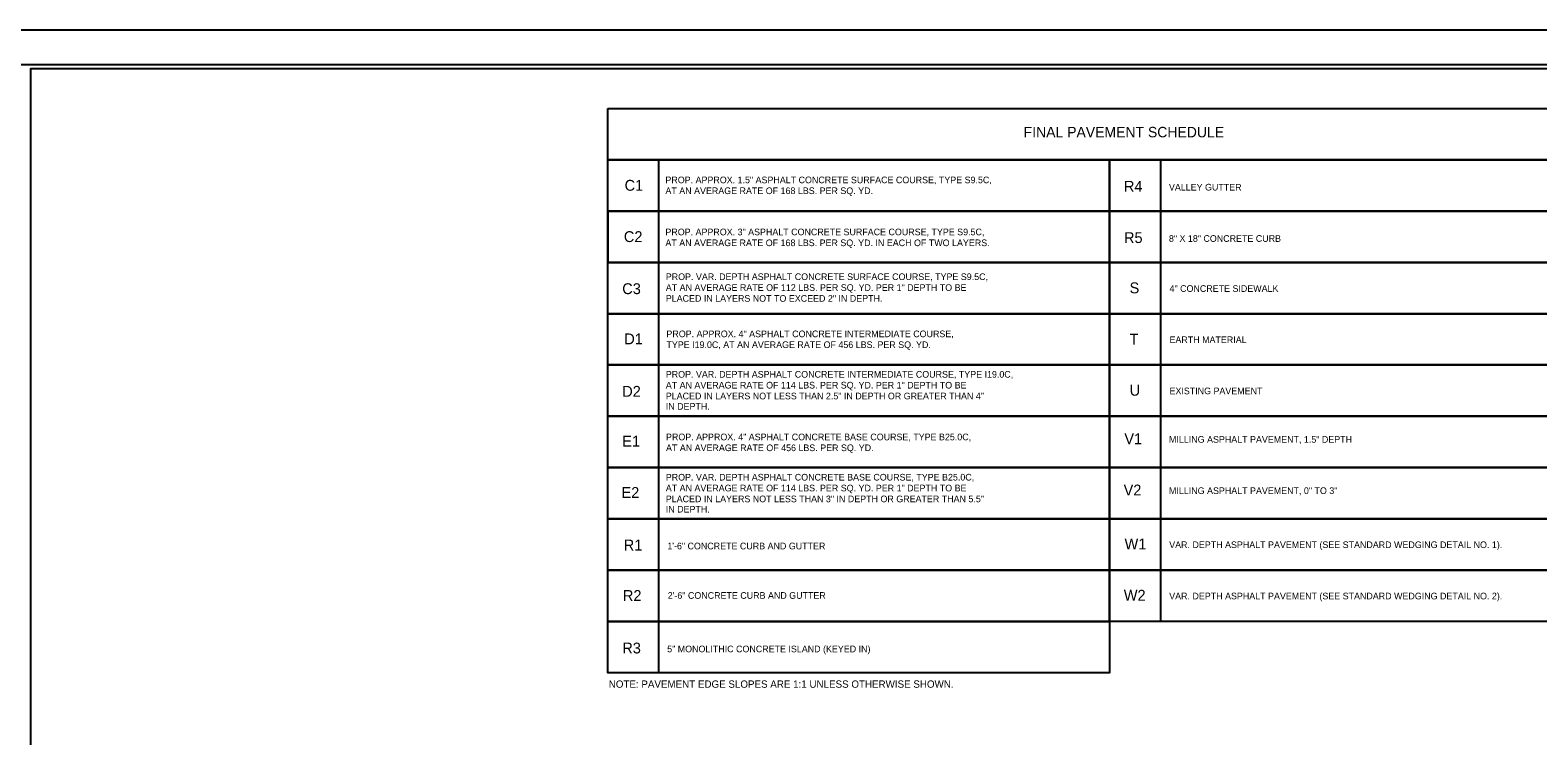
# Model space of a CAD drawing. Extents: x 957297 to 961629, y 830661 to 840840.
# Drawn here: x 958878 to 959856, y 840382 to 840840 of the extents above; entities that cross this region are included whole.
import ezdxf

# ---------------------------------------------------------------- set-up
doc = ezdxf.new("R2010")
doc.units = 0
for name, color, linetype in [('Old_Level_1', 7, 'Continuous'), ('Old_Level_19', 7, 'Continuous'), ('Old_Level_21', 7, 'Continuous'), ('Prop Pavement Schedule Description CELL', 7, 'Continuous'), ('Sheet Plot Border Inside CELL', 7, 'Continuous'), ('Sheet Plot Border Outside CELL', 7, 'Continuous'), ('Sheet Typical CELL', 7, 'Continuous')]:
    doc.layers.add(name, color=color, linetype=linetype)

msp = doc.modelspace()

# ---------------------------------------------------------------- linework, layer by layer
at = {"layer": 'Old_Level_1'}
msp.add_line((959252.25, 840722.31), (959252.25, 840689.02), dxfattribs=at)
at = {"layer": 'Old_Level_19'}
msp.add_lwpolyline([(959252.25, 840788.91), (959903.38, 840788.91), (959903.38, 840755.61), (959252.25, 840755.61)], close=True, dxfattribs=at)
for points in [[(959285.55, 840722.31), (959252.25, 840722.31), (959252.25, 840755.61), (959577.81, 840755.61), (959577.81, 840722.31), (959285.55, 840722.31), (959285.55, 840755.61)], [(959611.11, 840722.32), (959577.81, 840722.32), (959577.81, 840755.61), (959903.38, 840755.61), (959903.38, 840722.32), (959611.11, 840722.32), (959611.11, 840755.61)], [(959285.55, 840689.02), (959252.25, 840689.02), (959252.25, 840722.31), (959577.81, 840722.31), (959577.81, 840689.02), (959285.55, 840689.02), (959285.55, 840722.31)], [(959611.11, 840689.02), (959577.81, 840689.02), (959577.81, 840722.3), (959903.38, 840722.3), (959903.38, 840689.02), (959611.11, 840689.02), (959611.11, 840722.3)], [(959285.55, 840655.72), (959252.25, 840655.72), (959252.25, 840689.02), (959577.81, 840689.02), (959577.81, 840655.72), (959285.55, 840655.72), (959285.55, 840689.02)], [(959611.11, 840655.72), (959577.81, 840655.72), (959577.81, 840689.02), (959903.38, 840689.02), (959903.38, 840655.72), (959611.11, 840655.72), (959611.11, 840689.02)], [(959285.55, 840622.42), (959252.25, 840622.42), (959252.25, 840655.72), (959577.81, 840655.72), (959577.81, 840622.42), (959285.55, 840622.42), (959285.55, 840655.72)], [(959611.11, 840622.42), (959577.81, 840622.42), (959577.81, 840655.72), (959903.38, 840655.72), (959903.38, 840622.42), (959611.11, 840622.42), (959611.11, 840655.72)], [(959285.55, 840589.12), (959252.25, 840589.12), (959252.25, 840622.42), (959577.81, 840622.42), (959577.81, 840589.12), (959285.55, 840589.12), (959285.55, 840622.42)], [(959611.11, 840589.13), (959577.81, 840589.13), (959577.81, 840622.42), (959903.38, 840622.42), (959903.38, 840589.13), (959611.11, 840589.13), (959611.11, 840622.42)], [(959285.55, 840555.83), (959252.25, 840555.83), (959252.25, 840589.12), (959577.81, 840589.12), (959577.81, 840555.83), (959285.55, 840555.83), (959285.55, 840589.12)], [(959611.11, 840555.84), (959577.81, 840555.84), (959577.81, 840589.13), (959903.38, 840589.13), (959903.38, 840555.84), (959611.11, 840555.84), (959611.11, 840589.13)], [(959285.55, 840522.53), (959252.25, 840522.53), (959252.25, 840555.83), (959577.81, 840555.83), (959577.81, 840522.53), (959285.55, 840522.53), (959285.55, 840555.83)], [(959611.11, 840522.55), (959577.81, 840522.55), (959577.81, 840555.84), (959903.38, 840555.84), (959903.38, 840522.55), (959611.11, 840522.55), (959611.11, 840555.84)], [(959285.55, 840489.23), (959252.25, 840489.23), (959252.25, 840522.53), (959577.81, 840522.53), (959577.81, 840489.23), (959285.55, 840489.23), (959285.55, 840522.53)], [(959611.11, 840489.23), (959577.81, 840489.23), (959577.81, 840522.52), (959903.38, 840522.52), (959903.38, 840489.23), (959611.11, 840489.23), (959611.11, 840522.52)], [(959285.55, 840455.95), (959252.25, 840455.95), (959252.25, 840489.23), (959577.81, 840489.23), (959577.81, 840455.95), (959285.55, 840455.95), (959285.55, 840489.23)], [(959611.11, 840455.95), (959577.81, 840455.95), (959577.81, 840489.23), (959903.38, 840489.23), (959903.38, 840455.95), (959611.11, 840455.95), (959611.11, 840489.23)], [(959285.55, 840422.66), (959252.25, 840422.66), (959252.25, 840455.95), (959577.81, 840455.95), (959577.81, 840422.66), (959285.55, 840422.66), (959285.55, 840455.95)]]:
    msp.add_lwpolyline(points, dxfattribs=at)
at = {"layer": 'Sheet Plot Border Inside CELL'}
msp.add_lwpolyline([(960390.3, 840817.27), (958723.8, 840817.27), (958723.8, 839762.17), (960390.3, 839762.17)], close=True, dxfattribs=at)
at = {"layer": 'Sheet Plot Border Outside CELL'}
msp.add_lwpolyline([(960394.8, 840839.72), (958710.8, 840839.72), (958710.8, 839739.72), (960394.8, 839739.72)], close=True, dxfattribs=at)
at = {"layer": 'Sheet Typical CELL'}
msp.add_lwpolyline([(960377.8, 840814.72), (958877.8, 840814.72), (958877.8, 839764.72), (960377.8, 839764.72)], close=True, dxfattribs=at)

# ---------------------------------------------------------------- texts
at = {"layer": 'Old_Level_21'}
msp.add_text('FINAL PAVEMENT SCHEDULE', height=6.7824, dxfattribs=at).set_placement((959522.18, 840770.16))
at = {"layer": 'Prop Pavement Schedule Description CELL'}
for s, height, p in [('C1', 7.048, (959263.26, 840735.49)), ('AT AN AVERAGE RATE OF 168 LBS. PER SQ. YD. ', 4.3153, (959289.73, 840733.33)), ('PROP. APPROX. 1.5" ASPHALT CONCRETE SURFACE COURSE, TYPE S9.5C, ', 4.3153, (959289.73, 840740.37)), ('R4', 7.048, (959587.24, 840734.87)), ('VALLEY GUTTER', 4.3153, (959616.43, 840735.65)), ('C2', 7.048, (959262.77, 840702.2)), ('PROP. APPROX. 3" ASPHALT CONCRETE SURFACE COURSE, TYPE S9.5C, ', 4.3153, (959289.73, 840706.6)), ('R5', 7.048, (959587.28, 840701.56)), ('AT AN AVERAGE RATE OF 168 LBS. PER SQ. YD. IN EACH OF TWO LAYERS. ', 4.3153, (959289.73, 840699.55)), ('8" X 18" CONCRETE CURB', 4.3153, (959616.43, 840702.34)), ('PROP. VAR. DEPTH ASPHALT CONCRETE SURFACE COURSE, TYPE S9.5C, ', 4.3153, (959289.97, 840677.54)), ('C3', 7.048, (959261.73, 840668.4)), ('AT AN AVERAGE RATE OF 112 LBS. PER SQ. YD. PER 1" DEPTH TO BE ', 4.3153, (959289.97, 840670.5)), ('PLACED IN LAYERS NOT TO EXCEED 2" IN DEPTH.', 4.3153, (959289.97, 840663.46)), ('S', 7.05, (959590.9, 840668.94)), ('4" CONCRETE SIDEWALK', 4.3153, (959616.82, 840669.88)), ('D1', 7.048, (959263.02, 840635.84)), ('PROP. APPROX. 4" ASPHALT CONCRETE INTERMEDIATE COURSE, ', 4.3153, (959290.38, 840640.46)), ('T', 7.05, (959590.86, 840635.69)), ('EARTH MATERIAL', 4.3153, (959616.81, 840636.63)), ('TYPE I19.0C, AT AN AVERAGE RATE OF 456 LBS. PER SQ. YD. ', 4.3153, (959290.38, 840633.42)), ('AT AN AVERAGE RATE OF 114 LBS. PER SQ. YD. PER 1" DEPTH TO BE ', 4.3153, (959289.97, 840607.16)), ('PROP. VAR. DEPTH ASPHALT CONCRETE INTERMEDIATE COURSE, TYPE I19.0C, ', 4.3153, (959289.97, 840614.2)), ('U', 7.05, (959590.95, 840602.5)), ('D2', 7.048, (959261.69, 840601.8)), ('PLACED IN LAYERS NOT LESS THAN 2.5" IN DEPTH OR GREATER THAN 4" ', 4.3153, (959289.97, 840600.12)), ('EXISTING PAVEMENT', 4.3153, (959616.81, 840603.44)), ('IN DEPTH.', 4.315, (959289.97, 840593.42)), ('E1', 7.048, (959261.72, 840569.45)), ('AT AN AVERAGE RATE OF 456 LBS. PER SQ. YD. ', 4.3153, (959290.11, 840566.52)), ('PROP. APPROX. 4" ASPHALT CONCRETE BASE COURSE, TYPE B25.0C, ', 4.3153, (959290.11, 840573.56)), ('V1', 7.048, (959587.51, 840571.03)), ('MILLING ASPHALT PAVEMENT, 1.5" DEPTH', 4.3153, (959616.47, 840571.97)), ('PROP. VAR. DEPTH ASPHALT CONCRETE BASE COURSE, TYPE B25.0C, ', 4.3153, (959289.97, 840547.44)), ('E2', 7.048, (959261.23, 840536.16)), ('AT AN AVERAGE RATE OF 114 LBS. PER SQ. YD. PER 1" DEPTH TO BE ', 4.3153, (959289.97, 840540.4)), ('V2', 7.048, (959587.02, 840537.74)), ('MILLING ASPHALT PAVEMENT, 0" TO 3"', 4.3153, (959616.47, 840538.68)), ('PLACED IN LAYERS NOT LESS THAN 3" IN DEPTH OR GREATER THAN 5.5" ', 4.3153, (959289.97, 840533.36)), ('IN DEPTH.', 4.315, (959289.97, 840526.67)), ('R1', 7.048, (959262.68, 840502.03)), ('1\'-6" CONCRETE CURB AND GUTTER', 4.3153, (959290.98, 840502.78)), ('W1', 7.048, (959587.65, 840502.75)), ('VAR. DEPTH ASPHALT PAVEMENT (SEE STANDARD WEDGING DETAIL NO. 1).', 4.3153, (959616.61, 840503.61)), ('R2', 7.048, (959262.13, 840469.28)), ('2\'-6" CONCRETE CURB AND GUTTER', 4.3153, (959291.24, 840470.69)), ('W2', 7.048, (959587.16, 840469.46)), ('VAR. DEPTH ASPHALT PAVEMENT (SEE STANDARD WEDGING DETAIL NO. 2).', 4.3153, (959616.61, 840470.32)), ('R3', 7.048, (959261.75, 840435.21)), ('5" MONOLITHIC CONCRETE ISLAND (KEYED IN)', 4.3153, (959290.87, 840435.99)), ('NOTE: PAVEMENT EDGE SLOPES ARE 1:1 UNLESS OTHERWISE SHOWN.', 4.75, (959252.94, 840412.96))]:
    msp.add_text(s, height=height, dxfattribs=at).set_placement(p)

doc.saveas('drawing.dxf')
